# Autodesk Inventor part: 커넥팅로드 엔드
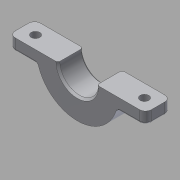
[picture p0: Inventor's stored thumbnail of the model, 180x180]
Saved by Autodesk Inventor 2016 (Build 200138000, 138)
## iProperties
Created: 2016-11
Part Number: 커넥팅로드 엔드
Material: 알루미늄 6061
Document SubType Name: Modeling
Designer: mduedu
Density: 2.71 g/cm^3
Mass: 24.1424 g
Surface Area: 36.9806 cm^2
Volume: 8.90864 cm^3
Appearance: 알루미늄 - 평지
Author: mduedu
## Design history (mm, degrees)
sketch "스케치1" dims "d0" = 42, "d3" = 20
  geometry: L1 (0, 0)-(0, 114); L2 (-7.5, 107.386)-(-12.5, 16.875); L3 (7.5, 107.386)-(12.5, 16.875); C1 r 10 at (0, 0); C2 r 6.5 at (0, 114); 3 further points
  constraints: 6 end point, 4 coincident, 2 centre point, 2 symmetric about line, 1 vertical, 6 other
  dimensions: "d1" = 20 diameter of C1; "d2" = 13 diameter of C2; "d4" = 114 distance of L1.start L1.end; "d6" = 12.5 distance from line of L1 L2.end; "d7" = 7.5 distance from line of L1 L2.start
extrude "돌출1" new body sketch "스케치1" stored distance "d8" = 13; taper "d9" = 0 deg
extrude "돌출2" join sketch "스케치1" stored distance "d10" = 20; taper "d11" = 0 deg
sketch "스케치2"
  geometry: L1 (-7.5, 107.386)-(-12.5, 16.875) reference; L2 (7.5, 107.386)-(12.5, 16.875) reference; A1 r 10 centre (0, 114) between (-7.5, 107.386) and (7.5, 107.386) reference; A2 r 21 centre (0, 0) between (-12.5, 16.875) and (12.5, 16.875) reference; 1 further point
extrude "돌출3" join sketch "스케치2" stored distance "d12" = 8; taper "d13" = 0 deg
sketch "스케치3"
  geometry: L1 (-7.5, 107.386)-(-12.5, 16.875) reference; L2 (7.5, 107.386)-(12.5, 16.875) reference; L3 (-4.209, 94.448)-(-7.768, 30.011); L4 (4.209, 94.448)-(7.768, 30.011); L5 (0, 94)-(0, 31); A1 r 10 centre (0, 114) between (-7.5, 107.386) and (7.5, 107.386) reference; A2 r 21 centre (0, 0) between (-12.5, 16.875) and (12.5, 16.875) reference; A3 r 20 centre (0, 114) between (-4.209, 94.448) and (4.209, 94.448); A4 r 31 centre (0, 0) between (7.768, 30.011) and (-7.768, 30.011); 1 further point
  constraints: 6 end point, 6 point on circle, 2 centre point, 2 parallel, 1 symmetric about line, 1 vertical alignment
  dimensions: "d18" = 10 radial gap between concentric circles of A3 A1; "d19" = 10 radial gap between concentric circles of A2 A4; "d20" = 4 distance between parallel lines of L3 L1
extrude "돌출4" cut sketch "스케치3" distance "d21" = 2; taper "d22" = 0 deg
fillet "모깎기1" dims "d23" = 3
fillet "모깎기2" dims "d24" = 2
fillet "모깎기3" dims "d25" = 2
chamfer "모따기1" distance "d26" = 1; stored, may be unused: second distance "d27" = 2, angle "d28" = 45 deg
sketch "스케치4"
  geometry: L1 (-35, -6)-(-20.125, -6); L2 (35, -6)-(35, 6); L3 (35, 6)-(20.125, 6); L4 (-35, 6)-(-35, -6); L5 (-35, -6)-(35, 6); L6 (35, -6)-(-35, 6); L7 (-20.125, 6)-(-35, 6); L8 (20.125, 6)-(-20.125, 6); L9 (20.125, -6)-(35, -6); L10 (-20.125, -6)-(20.125, -6); A1 r 21 centre (0, 0) between (-20.125, 6) and (20.125, 6) reference; 1 further point
  constraints: 20 end point, 10 parallel, 4 point on circle, 3 horizontal, 3 perpendicular, 2 midpoint
  dimensions: "d29" = 70 distance of L1.start L2.start; "d31" = 12 distance of L2.start L2.end
extrude "돌출5" join sketch "스케치4" stored distance "d32" = 0; taper "d33" = 0 deg
fillet "모깎기4" dims "d34" = 3
fillet "모깎기5" dims "d35" = 1
fillet "모깎기6" dims "d36" = 1
sketch "스케치5"
  geometry: L1 (1, 0)-(1, 7) reference; L2 (-24, 13.5)-(-44, 13.5) reference; L3 (-44, -6.5)-(-24, -6.5) reference; L4 (-34, 13.5)-(-34, -6.5); 3 further points
  constraints: 2 end point, 2 midpoint, 1 horizontal alignment, 1 symmetric about line
  dimensions: "d37" = 7 distance from line of point (-6, 3.5) L1
feature "분할1"
sketch "스케치6"
  geometry: 2 further points
  constraints: 2 other
hole "구멍1" sketch "스케치6" at (-62, 3.5), (-6, 3.5) diameter "d38" = 4.5; stored, may be unused: countersink angle "d42" = 90 deg, drill point angle "d44" = 0 deg; dims "d39" = 6, "d40" = 4, "d41" = 2, "d43" = 8
node "솔리드1"
mirror "대칭1"
other parameters: "d16" = 4, "d17" = 4
